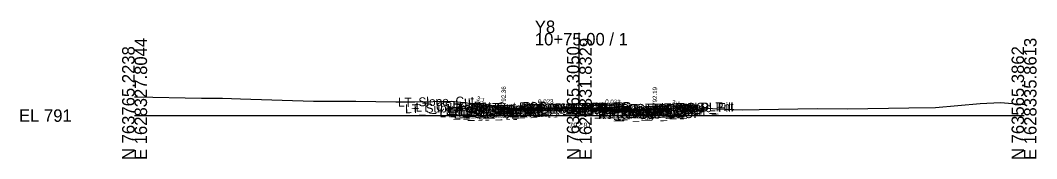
# Model space of a CAD drawing. Extents: x -26 to 203, y -10 to 3017.
# Drawn here: x -25.7 to 202.8, y 1490.3 to 1521.4 of the extents above; entities that cross this region are included whole.
import ezdxf

# ---------------------------------------------------------------- set-up
doc = ezdxf.new("R2010")
doc.units = 0
for name, color, linetype in [('Default', 7, 'Continuous'), ('Exist CMT Pavement', 7, 'Continuous'), ('Exist Cross Section Cell', 7, 'Continuous'), ('Exist XS Center Line Elevation Label', 7, 'Continuous'), ('Exist XS Ground Line', 7, 'Continuous'), ('Prop CMT Conc Surface', 7, 'Continuous'), ('Prop CMT Concrete Structures', 7, 'Continuous'), ('Prop CMT Pvmt Course 1', 7, 'Continuous'), ('Prop CMT Pvmt Course 1 CG', 7, 'Continuous'), ('Prop CMT Pvmt Course 1 Wedge', 7, 'Continuous'), ('Prop CMT Pvmt Course 2', 7, 'Continuous'), ('Prop CMT Pvmt Course 2 Wedge', 7, 'Continuous'), ('Prop CMT Pvmt Course 3', 7, 'Continuous'), ('Prop CMT Pvmt Surface', 7, 'Continuous'), ('Prop CMT Pvmt Wedge Surface 1', 7, 'Continuous'), ('Prop CMT Pvmt Wedge Surface 2', 7, 'Continuous'), ('Prop CMT Pvmt Wedge Surface 3', 7, 'Continuous'), ('Prop CMT Slope Grass', 7, 'Continuous'), ('Prop CMT Subgrade Earthwork', 7, 'Continuous'), ('Prop XS Hydro Elevations', 7, 'Continuous'), ('Prop XS SE Text', 7, 'Continuous'), ('Prop XS Side Slope Text', 7, 'Continuous'), ('Scratch_Level_0', 7, 'Continuous')]:
    doc.layers.add(name, color=color, linetype=linetype)

msp = doc.modelspace()

# ---------------------------------------------------------------- linework, layer by layer
at = {"layer": 'Exist CMT Pavement'}
for points in [[(100, 1501.81), (91.13, 1501.47), (85, 1501.22)], [(100, 1501.81), (100.34, 1501.82), (111.58, 1501.29), (115, 1501.12)]]:
    msp.add_lwpolyline(points, dxfattribs=at)
at = {"layer": 'Exist Cross Section Cell'}
for p, q in [((100, 1500), (100, 1518.58)), ((0, 1500), (100, 1500)), ((100, 1500), (200, 1500))]:
    msp.add_line(p, q, dxfattribs=at)
at = {"layer": 'Exist XS Ground Line'}
msp.add_lwpolyline([(0, 1504.19), (0.44, 1504.18), (15.02, 1503.94), (19.75, 1503.88), (23.81, 1503.79), (40.24, 1503.26), (49.77, 1503.24), (58.71, 1503.12), (62.98, 1503.1), (71.25, 1503.22), (75.55, 1502.81), (78.38, 1502.69), (81.09, 1502.08), (84.33, 1501.47), (84.76, 1501.21), (91.13, 1501.47), (100, 1501.81), (100.34, 1501.82), (111.58, 1501.29), (115.14, 1501.12), (115.5, 1501.42), (118.24, 1501.65), (127.98, 1501.76), (130.95, 1501.49), (136.73, 1501.32), (140.46, 1501.37), (153.46, 1501.58), (160.34, 1501.49), (174.1, 1501.71), (180.06, 1501.82), (190.13, 1502.73), (194.69, 1502.95), (197.44, 1502.71), (200, 1502.52)], dxfattribs=at)
at = {"layer": 'Prop CMT Conc Surface'}
for points in [[(83, 1501.36), (83, 1501.86), (82.5, 1501.86)], [(85, 1501.49), (83, 1501.36)], [(117, 1501.19), (117, 1501.69), (117.5, 1501.69)], [(115, 1501.34), (117, 1501.19)]]:
    msp.add_lwpolyline(points, dxfattribs=at)
at = {"layer": 'Prop CMT Concrete Structures'}
for points in [[(85, 1501.49), (83, 1501.36), (83, 1501.86), (82.5, 1501.86)], [(82.5, 1501.86), (82.5, 1500.85), (85, 1500.91)], [(85, 1500.91), (85, 1501.49)], [(115, 1501.34), (117, 1501.19), (117, 1501.69), (117.5, 1501.69)], [(117.5, 1501.69), (117.5, 1500.67), (115, 1500.76)], [(115, 1500.76), (115, 1501.34)]]:
    msp.add_lwpolyline(points, dxfattribs=at)
at = {"layer": 'Prop CMT Pvmt Course 1'}
for points in [[(100, 1501.84), (85, 1501.49)], [(85, 1501.37), (100, 1501.72)], [(85, 1501.49), (85, 1501.24), (85, 1501.24), (85, 1501.37)], [(100, 1501.59), (100, 1501.84)], [(100, 1501.84), (115, 1501.34)], [(100, 1501.59), (100, 1501.84)], [(100, 1501.72), (100, 1501.59), (100, 1501.59)], [(115, 1501.21), (100, 1501.72)], [(100, 1501.72), (100, 1501.59), (100, 1501.59)], [(115, 1501.34), (115, 1501.09), (115, 1501.09), (115, 1501.21)]]:
    msp.add_lwpolyline(points, dxfattribs=at)
at = {"layer": 'Prop CMT Pvmt Course 1 CG'}
for points in [[(85, 1500.91), (82, 1500.84), (81.66, 1500.5)], [(81.66, 1500.5), (85, 1500.57)], [(85, 1500.57), (85, 1500.91)], [(115, 1500.76), (118, 1500.66), (118.34, 1500.31)], [(115, 1500.42), (115, 1500.76)], [(118.34, 1500.31), (115, 1500.42)]]:
    msp.add_lwpolyline(points, dxfattribs=at)
at = {"layer": 'Prop CMT Pvmt Course 1 Wedge'}
for points in [[(85, 1501.37), (91.13, 1501.51), (93.96, 1501.57)], [(93.96, 1501.57), (91.13, 1501.47), (86.33, 1501.27), (85, 1501.24)], [(85, 1501.24), (85, 1501.37)], [(115, 1501.12), (111.58, 1501.29), (108.69, 1501.43)], [(108.69, 1501.43), (111.58, 1501.33)], [(111.58, 1501.33), (115, 1501.21)], [(115, 1501.21), (115, 1501.12)]]:
    msp.add_lwpolyline(points, dxfattribs=at)
at = {"layer": 'Prop CMT Pvmt Course 2'}
for points in [[(85, 1500.91), (85, 1500.91), (85, 1501.24), (85, 1501.24)], [(85, 1501.24), (85, 1500.91)], [(115, 1500.76), (115, 1500.76), (115, 1501.09), (115, 1501.09)], [(115, 1501.09), (115, 1500.76)]]:
    msp.add_lwpolyline(points, dxfattribs=at)
at = {"layer": 'Prop CMT Pvmt Course 2 Wedge'}
for points in [[(85, 1501.24), (86.33, 1501.27)], [(86.33, 1501.27), (85, 1501.22)], [(85, 1501.22), (85, 1501.24)]]:
    msp.add_lwpolyline(points, dxfattribs=at)
at = {"layer": 'Prop CMT Pvmt Course 3'}
for points in [[(85, 1500.91), (85, 1500.91), (85, 1500.57), (85, 1500.57)], [(85, 1500.57), (85, 1500.91)], [(115, 1500.76), (115, 1500.76), (115, 1500.42), (115, 1500.42)], [(115, 1500.42), (115, 1500.76)]]:
    msp.add_lwpolyline(points, dxfattribs=at)
at = {"layer": 'Prop CMT Pvmt Surface'}
for points in [[(100, 1501.84), (85, 1501.49)], [(100, 1501.84), (115, 1501.34)]]:
    msp.add_lwpolyline(points, dxfattribs=at)
at = {"layer": 'Prop CMT Pvmt Wedge Surface 1'}
for points in [[(100, 1501.72), (85, 1501.37)], [(85, 1501.24), (85, 1501.49)], [(100, 1501.72), (115, 1501.21)], [(85, 1501.37), (85, 1501.24), (85, 1501.24)], [(115, 1501.09), (115, 1501.34)], [(115, 1501.21), (115, 1501.09), (115, 1501.09)]]:
    msp.add_lwpolyline(points, dxfattribs=at)
at = {"layer": 'Prop CMT Pvmt Wedge Surface 2'}
for points in [[(100, 1501.59), (85, 1501.24)], [(85, 1501.24), (85, 1501.49)], [(100, 1501.59), (115, 1501.09)], [(115, 1501.09), (115, 1501.34)]]:
    msp.add_lwpolyline(points, dxfattribs=at)
at = {"layer": 'Prop CMT Pvmt Wedge Surface 3'}
for points in [[(85, 1500.91), (85, 1501.49)], [(100, 1501.26), (85, 1500.91)], [(100, 1501.26), (115, 1500.76)], [(115, 1500.76), (115, 1501.34)]]:
    msp.add_lwpolyline(points, dxfattribs=at)
at = {"layer": 'Prop CMT Slope Grass'}
for points in [[(79, 1501.93), (76.5, 1502.77)], [(82.5, 1501.86), (79, 1501.93)], [(117.5, 1501.69), (121, 1501.76)], [(121, 1501.76), (121.24, 1501.68)]]:
    msp.add_lwpolyline(points, dxfattribs=at)
at = {"layer": 'Prop CMT Subgrade Earthwork'}
for points in [[(85, 1500.57), (81.66, 1500.5), (80.25, 1501.91)], [(115, 1500.42), (118.34, 1500.31), (119.77, 1501.74)], [(85, 1500.57), (85.01, 1501.22)], [(85, 1500.57), (85, 1500.57)], [(115, 1500.42), (114.98, 1501.12)], [(115, 1500.42), (115, 1500.42)]]:
    msp.add_lwpolyline(points, dxfattribs=at)

# ---------------------------------------------------------------- texts
at = {"layer": 'Default'}
msp.add_text('-', height=0.0001, dxfattribs=at).set_placement((0, 1500))
at = {"layer": 'Exist Cross Section Cell'}
for s, p in [('Y8', (90, 1518.58)), ('10+75.00 / 1', (90, 1515.78)), ('EL 791', (-26, 1498.6))]:
    msp.add_text(s, height=2.8, dxfattribs=at).set_placement(p)
for s, p in [('N 763765.2238', (0, 1490)), ('E 1628327.8044', (2.8, 1490)), ('N 763665.3050', (100, 1490)), ('E 1628331.8329', (102.8, 1490)), ('N 763565.3862', (200, 1490)), ('E 1628335.8613', (202.8, 1490))]:
    msp.add_text(s, height=2.8, rotation=90, dxfattribs=at).set_placement(p)
at = {"layer": 'Exist XS Center Line Elevation Label'}
msp.add_text('792.81', height=1.2, dxfattribs=at).set_placement((97.7, 1497.21))
at = {"layer": 'Prop XS Hydro Elevations'}
for s, p in [('792.36', (83.5, 1502.36)), ('792.19', (117.5, 1502.19))]:
    msp.add_text(s, height=1, rotation=90, dxfattribs=at).set_placement(p)
at = {"layer": 'Prop XS SE Text'}
for s, rotation, p in [('0.023', 1.3367, (90.75, 1502.62)), ('0.033', 358.0908, (105.81, 1502.65))]:
    msp.add_text(s, height=1, rotation=rotation, dxfattribs=at).set_placement(p)
at = {"layer": 'Prop XS Side Slope Text'}
for p in [(76.78, 1503.46), (120.68, 1502.66)]:
    msp.add_text('3:1', height=1, rotation=341.5668, dxfattribs=at).set_placement(p)
at = {"layer": 'Scratch_Level_0'}
for s, p in [('LT_Slope_Cut', (59.24, 1501.99)), ('LT_Sub_Trench_Out_DLT', (60.84, 1500.52)), ('LT_CSLP_Pnt', (63.19, 1500.86)), ('LT_CG1_Shelf_Out', (68.57, 1499.57)), ('LT_PV_Sub_Tie_Out', (69.98, 1499.92)), ('LT_CG_Top_Face', (70.28, 1500.61)), ('LT_CG_Top_BOC', (70.8, 1500.63)), ('LT_CG_Bot_BOC', (70.84, 1499.61)), ('LT_CG_Top_Gut', (71.26, 1500.13)), ('LT_Sub_OEOP', (71.79, 1499.3)), ('LT_PV_OEEOP_EG', (72.57, 1499.97)), ('LT_Sub_OEEOP', (74.23, 1499.36)), ('LT_PV2_OEEOP', (74.33, 1500.03)), ('LT_PV3_OEEOP', (74.33, 1499.69)), ('LT_PV1_OEEOP', (74.9, 1500.16)), ('LT_CG_Bot_IE', (74.94, 1499.71)), ('LT_Sub_OEOT', (75.1, 1499.38)), ('LT_PV2_OEOT', (75.2, 1500.04)), ('LT_PV3_OEOT', (75.2, 1499.71)), ('LT_PV1_OEOT', (75.76, 1500.31)), ('RT_PV_IEEOP_EG', (88.16, 1500.57)), ('LT_PV_IEEOP_EG', (88.21, 1500.57)), ('RT_PV2_IEEOP', (89.93, 1500.39)), ('RT_PV3_IEEOP', (89.93, 1500.05)), ('LT_PV2_IEEOP', (89.97, 1500.39)), ('LT_PV3_IEEOP', (89.97, 1500.06)), ('RT_PV1_IEEOP', (90.49, 1500.52)), ('LT_PV1_IEEOP', (90.54, 1500.53)), ('PV2_PGL', (93.93, 1500.47)), ('PV1_PGL', (94.49, 1500.73)), ('RT_PV_Sub_Tie_Out', (99.91, 1499.82)), ('RT_Sub_Trench_Out_DLT', (100.32, 1500.35)), ('RT_PV_OEEOP_EG', (102.52, 1499.87)), ('RT_Sub_OEEOP', (104.19, 1499.21)), ('RT_CG_Top_Face', (104.24, 1500.44)), ('RT_PV2_OEEOP', (104.28, 1499.88)), ('RT_PV3_OEEOP', (104.28, 1499.54)), ('RT_CG1_Shelf_Out', (104.53, 1499.39)), ('RT_PV1_OEEOP', (104.85, 1500.01)), ('RT_CG_Bot_IE', (104.89, 1499.55)), ('RT_Sub_OEOT', (105.05, 1499.22)), ('RT_PV2_OEOT', (105.15, 1499.89)), ('RT_PV3_OEOT', (105.15, 1499.56)), ('RT_CG_Top_Gut', (105.21, 1499.96)), ('RT_PV1_OEOT', (105.71, 1500.15)), ('RT_CG_Top_BOC', (105.76, 1500.46)), ('RT_CG_Bot_BOC', (105.79, 1499.44)), ('RT_Sub_OEOP', (108.43, 1499.11)), ('RT_CSLP_Pnt', (117.15, 1500.69)), ('RT_Slope_Fill', (117.88, 1500.56))]:
    msp.add_text(s, height=2, rotation=1.1458, dxfattribs=at).set_placement(p)

doc.saveas('drawing.dxf')
